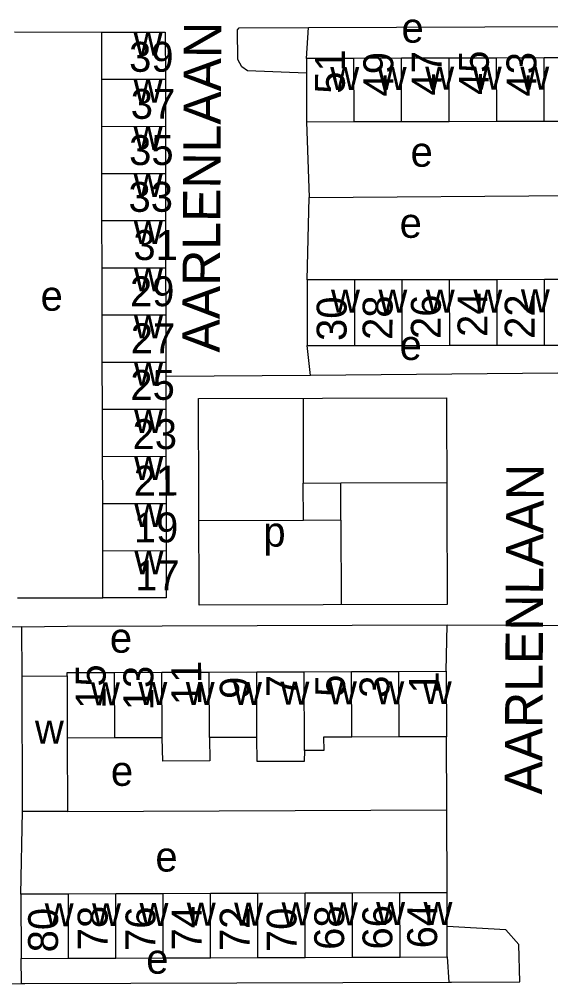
# Model space of a CAD drawing. Extents: x 159675 to 162108, y 386471 to 388472.
# Drawn here: x 161529.2 to 161600.3, y 388087.9 to 388216.9 of the extents above; entities that cross this region are included whole.
import ezdxf

# ---------------------------------------------------------------- set-up
doc = ezdxf.new("R2010")
doc.units = 0
for name, color, linetype in [('BLT_Basislijn', 7, 'Continuous'), ('BLT_Bebouwing', 7, 'Continuous'), ('BLT_Centroide', 7, 'Continuous'), ('BLT_Huisnummer', 7, 'Continuous'), ('BLT_Huisnummer_ tussenligend', 7, 'Continuous'), ('BLT_Onderverdeling_panden', 7, 'Continuous'), ('BLT_Straatnaam', 7, 'Continuous')]:
    doc.layers.add(name, color=color, linetype=linetype)

msp = doc.modelspace()

# ---------------------------------------------------------------- linework, layer by layer
at = {"layer": 'BLT_Basislijn'}
for p, q in [((161567.59, 388211.63), (161567.87, 388215.79)), ((161567.87, 388215.79), (161605.81, 388215.9)), ((161528.53, 388215.18), (161540.24, 388215.17)), ((161567.61, 388203.17), (161567.94, 388193.05)), ((161567.7, 388182.01), (161567.94, 388193.05)), ((161567.94, 388193.05), (161605.87, 388193.33)), ((161568.12, 388169.25), (161567.71, 388173.26)), ((161568.12, 388169.25), (161548.78, 388169.09)), ((161567.14, 388166.19), (161567.17, 388154.85)), ((161567.17, 388154.85), (161572.2, 388154.86)), ((161567.19, 388149.86), (161567.17, 388154.85)), ((161572.2, 388154.86), (161586.34, 388154.91)), ((161572.21, 388149.88), (161572.2, 388154.86)), ((161567.19, 388149.86), (161553.22, 388149.82)), ((161572.21, 388149.88), (161567.19, 388149.86)), ((161572.21, 388149.88), (161572.25, 388138.57)), ((161528.96, 388139.51), (161540.37, 388139.49)), ((161529.58, 388129.04), (161529.54, 388135.64)), ((161586.3, 388129.68), (161586.4, 388135.88)), ((161586.4, 388135.88), (161605.8, 388135.8)), ((161586.37, 388111.14), (161586.34, 388120.92)), ((161529.41, 388099.86), (161529.61, 388110.92)), ((161535.65, 388110.94), (161586.37, 388111.14)), ((161586.4, 388100.05), (161586.37, 388111.14)), ((161586.43, 388091.47), (161586.63, 388088.09)), ((161529.5, 388087.93), (161529.44, 388091.28))]:
    msp.add_line(p, q, dxfattribs=at)
for points in [[(161567.59, 388209.65), (161559.7, 388210), (161558.94, 388210.54), (161558.4, 388211.52), (161558.36, 388215.46), (161558.59, 388215.72), (161567.87, 388215.79)], [(161607.33, 388169.45), (161605.92, 388169.6), (161568.12, 388169.25)], [(161529.54, 388135.64), (161521.68, 388135.58), (161520.91, 388135.58)], [(161529.54, 388135.64), (161535.59, 388135.69), (161586.4, 388135.88)], [(161586.63, 388088.09), (161586.99, 388088.09), (161596.14, 388088.14), (161596.01, 388093.14), (161594.27, 388095.11), (161586.42, 388095.55)], [(161521.72, 388087.89), (161522.06, 388087.89), (161529.5, 388087.93)], [(161529.5, 388087.93), (161529.91, 388087.94), (161586.63, 388088.09)]]:
    msp.add_lwpolyline(points, dxfattribs=at)
msp.add_lwpolyline([(161553.16, 388166.16), (161586.32, 388166.27), (161586.41, 388138.6), (161553.24, 388138.5)], close=True, dxfattribs=at)
at = {"layer": 'BLT_Bebouwing'}
for p, q in [((161540.23, 388208.86), (161540.24, 388215.17)), ((161540.24, 388215.17), (161548.72, 388215.15)), ((161548.72, 388215.15), (161548.73, 388208.88)), ((161573.94, 388211.65), (161567.59, 388211.63)), ((161567.59, 388211.63), (161567.59, 388209.65)), ((161580.3, 388211.67), (161573.94, 388211.65)), ((161586.66, 388211.69), (161580.3, 388211.67)), ((161593.01, 388211.7), (161586.66, 388211.69)), ((161599.37, 388211.72), (161593.01, 388211.7)), ((161605.72, 388211.74), (161599.37, 388211.72)), ((161540.22, 388202.56), (161540.23, 388208.86)), ((161548.73, 388208.88), (161548.74, 388202.57)), ((161567.59, 388209.65), (161567.61, 388203.17)), ((161548.74, 388202.57), (161548.74, 388196.27)), ((161567.61, 388203.17), (161573.97, 388203.19)), ((161573.97, 388203.19), (161580.32, 388203.21)), ((161580.32, 388203.21), (161586.68, 388203.22)), ((161586.68, 388203.22), (161593.04, 388203.24)), ((161593.04, 388203.24), (161599.39, 388203.26)), ((161599.39, 388203.26), (161605.75, 388203.28)), ((161540.24, 388189.95), (161540.23, 388196.25)), ((161548.74, 388196.27), (161548.75, 388189.96)), ((161540.26, 388183.64), (161540.24, 388189.95)), ((161548.75, 388189.96), (161548.76, 388183.65)), ((161540.28, 388177.33), (161540.26, 388183.64)), ((161548.76, 388183.65), (161548.77, 388177.35)), ((161574.05, 388182.02), (161567.7, 388182.01)), ((161567.7, 388182.01), (161567.71, 388173.26)), ((161580.39, 388182.03), (161574.05, 388182.02)), ((161586.74, 388182.04), (161580.39, 388182.03)), ((161593.08, 388182.05), (161586.74, 388182.04)), ((161599.43, 388182.06), (161593.08, 388182.05)), ((161605.77, 388182.07), (161599.43, 388182.06)), ((161540.29, 388171.03), (161540.28, 388177.33)), ((161548.77, 388177.35), (161548.78, 388171.04)), ((161567.71, 388173.26), (161574.06, 388173.27)), ((161574.06, 388173.27), (161580.4, 388173.27)), ((161580.4, 388173.27), (161586.75, 388173.28)), ((161586.75, 388173.28), (161593.09, 388173.29)), ((161593.09, 388173.29), (161599.44, 388173.3)), ((161599.44, 388173.3), (161605.78, 388173.31)), ((161540.31, 388164.72), (161540.29, 388171.03)), ((161548.78, 388171.04), (161548.78, 388169.09)), ((161548.78, 388169.09), (161548.79, 388164.74)), ((161540.32, 388158.42), (161540.31, 388164.72)), ((161548.79, 388164.74), (161548.8, 388158.43)), ((161540.34, 388152.11), (161540.32, 388158.42)), ((161548.8, 388158.43), (161548.81, 388152.12)), ((161540.36, 388145.8), (161540.34, 388152.11)), ((161548.81, 388152.12), (161548.82, 388145.82)), ((161540.37, 388139.49), (161540.36, 388145.8)), ((161529.58, 388129.04), (161535.59, 388129.06)), ((161529.61, 388110.92), (161529.58, 388129.04)), ((161541.92, 388129.52), (161548.26, 388129.55)), ((161548.26, 388129.55), (161554.6, 388129.57)), ((161554.6, 388129.57), (161560.94, 388129.59)), ((161560.94, 388129.59), (161567.28, 388129.61)), ((161567.28, 388129.61), (161573.63, 388129.63)), ((161573.63, 388129.63), (161579.97, 388129.66)), ((161579.97, 388129.66), (161586.3, 388129.68)), ((161586.3, 388129.68), (161586.34, 388120.92)), ((161541.95, 388120.77), (161535.61, 388120.74)), ((161535.61, 388120.74), (161535.65, 388110.94)), ((161548.29, 388120.79), (161541.95, 388120.77)), ((161560.97, 388120.83), (161554.63, 388120.81)), ((161580, 388120.9), (161573.66, 388120.88)), ((161535.75, 388099.88), (161529.41, 388099.86)), ((161529.41, 388099.86), (161529.44, 388091.28)), ((161542.08, 388099.9), (161535.75, 388099.88)), ((161548.41, 388099.92), (161542.08, 388099.9)), ((161554.75, 388099.94), (161548.41, 388099.92)), ((161561.08, 388099.97), (161554.75, 388099.94)), ((161567.41, 388099.99), (161561.08, 388099.97)), ((161573.74, 388100.01), (161567.41, 388099.99)), ((161580.08, 388100.03), (161573.74, 388100.01)), ((161586.4, 388100.05), (161580.08, 388100.03)), ((161586.42, 388095.55), (161586.4, 388100.05)), ((161586.43, 388091.47), (161586.42, 388095.55)), ((161580.11, 388091.45), (161586.43, 388091.47)), ((161529.44, 388091.28), (161535.78, 388091.3)), ((161535.78, 388091.3), (161542.11, 388091.32)), ((161542.11, 388091.32), (161548.44, 388091.34)), ((161548.44, 388091.34), (161554.77, 388091.36)), ((161554.77, 388091.36), (161561.11, 388091.38)), ((161561.11, 388091.38), (161567.44, 388091.41)), ((161567.44, 388091.41), (161573.77, 388091.43)), ((161573.77, 388091.43), (161580.11, 388091.45))]:
    msp.add_line(p, q, dxfattribs=at)
for points in [[(161540.23, 388196.25), (161540.22, 388199.86), (161540.22, 388202.56)], [(161548.82, 388145.82), (161548.82, 388139.52), (161540.37, 388139.49)], [(161535.59, 388129.06), (161535.59, 388129.5), (161541.92, 388129.52)], [(161554.63, 388120.81), (161554.68, 388117.69), (161548.39, 388117.67), (161548.29, 388120.79)], [(161567.32, 388119.07), (161567.3, 388117.61), (161560.99, 388117.59), (161560.97, 388120.83)], [(161573.66, 388120.88), (161569.89, 388120.86), (161569.9, 388119.08), (161567.32, 388119.07)], [(161586.34, 388120.92), (161581.34, 388120.91), (161580, 388120.9)], [(161535.65, 388110.94), (161534.61, 388110.93), (161529.61, 388110.92)]]:
    msp.add_lwpolyline(points, dxfattribs=at)
at = {"layer": 'BLT_Onderverdeling_panden'}
for p, q in [((161573.97, 388203.19), (161573.94, 388211.65)), ((161580.32, 388203.21), (161580.3, 388211.67)), ((161586.68, 388203.22), (161586.66, 388211.69)), ((161593.04, 388203.24), (161593.01, 388211.7)), ((161599.39, 388203.26), (161599.37, 388211.72)), ((161540.23, 388208.86), (161548.73, 388208.88)), ((161540.22, 388202.56), (161548.74, 388202.57)), ((161540.23, 388196.25), (161548.74, 388196.27)), ((161540.24, 388189.95), (161548.75, 388189.96)), ((161540.26, 388183.64), (161548.76, 388183.65)), ((161574.06, 388173.27), (161574.05, 388182.02)), ((161580.4, 388173.27), (161580.39, 388182.03)), ((161586.75, 388173.28), (161586.74, 388182.04)), ((161593.09, 388173.29), (161593.08, 388182.05)), ((161599.44, 388173.3), (161599.43, 388182.06)), ((161540.28, 388177.33), (161548.77, 388177.35)), ((161540.29, 388171.03), (161548.78, 388171.04)), ((161540.31, 388164.72), (161548.79, 388164.74)), ((161540.32, 388158.42), (161548.8, 388158.43)), ((161540.34, 388152.11), (161548.81, 388152.12)), ((161540.36, 388145.8), (161548.82, 388145.82)), ((161535.59, 388129.06), (161535.61, 388120.74)), ((161541.95, 388120.77), (161541.92, 388129.52)), ((161548.29, 388120.79), (161548.26, 388129.55)), ((161554.63, 388120.81), (161554.6, 388129.57)), ((161560.97, 388120.83), (161560.94, 388129.59)), ((161567.32, 388119.07), (161567.28, 388129.61)), ((161573.66, 388120.88), (161573.63, 388129.63)), ((161580, 388120.9), (161579.97, 388129.66)), ((161535.78, 388091.3), (161535.75, 388099.88)), ((161542.11, 388091.32), (161542.08, 388099.9)), ((161548.44, 388091.34), (161548.41, 388099.92)), ((161554.77, 388091.36), (161554.75, 388099.94)), ((161561.11, 388091.38), (161561.08, 388099.97)), ((161567.44, 388091.41), (161567.41, 388099.99)), ((161573.77, 388091.43), (161573.74, 388100.01)), ((161580.11, 388091.45), (161580.08, 388100.03))]:
    msp.add_line(p, q, dxfattribs=at)

# ---------------------------------------------------------------- texts
at = {"layer": 'BLT_Centroide'}
for s, p in [('e', (161580.31, 388213.75)), ('w', (161544.48, 388212.03)), ('w', (161570.78, 388207.41)), ('w', (161577.12, 388207.42)), ('w', (161583.48, 388207.45)), ('w', (161589.84, 388207.45)), ('w', (161596.2, 388207.48)), ('w', (161544.48, 388205.72)), ('w', (161544.48, 388199.41)), ('e', (161581.52, 388197.16)), ('w', (161544.49, 388193.09)), ('e', (161580.06, 388187.65)), ('w', (161544.51, 388186.81)), ('w', (161544.52, 388180.5)), ('e', (161532.04, 388177.9)), ('w', (161570.88, 388177.64)), ('w', (161577.22, 388177.66)), ('w', (161583.56, 388177.66)), ('w', (161589.92, 388177.66)), ('w', (161596.27, 388177.69)), ('w', (161544.53, 388174.19)), ('e', (161580.06, 388171.31)), ('w', (161544.54, 388167.88)), ('w', (161544.55, 388161.56)), ('w', (161544.56, 388155.28)), ('w', (161544.58, 388148.97)), ('p', (161561.83, 388146.35)), ('w', (161544.59, 388142.66)), ('e', (161541.3, 388132.16)), ('w', (161538.77, 388125.12)), ('w', (161545.11, 388125.16)), ('w', (161551.45, 388125.19)), ('w', (161557.78, 388125.19)), ('w', (161564.12, 388125.22)), ('w', (161570.47, 388125.25)), ('w', (161576.81, 388125.27)), ('w', (161583.16, 388125.28)), ('w', (161531.28, 388120)), ('e', (161541.44, 388114.35)), ('e', (161547.39, 388102.89)), ('w', (161532.59, 388095.58)), ('w', (161538.92, 388095.59)), ('w', (161545.27, 388095.62)), ('w', (161551.59, 388095.64)), ('w', (161557.92, 388095.67)), ('w', (161564.27, 388095.69)), ('w', (161570.59, 388095.7)), ('w', (161576.92, 388095.73)), ('w', (161583.25, 388095.75)), ('e', (161546.17, 388089.23))]:
    msp.add_text(s, height=4, dxfattribs=at).set_placement(p)
at = {"layer": 'BLT_Huisnummer'}
for s, rotation, p in [('39', 0.183, (161543.88, 388209.85)), ('51', 89.8307, (161572.72, 388206.92)), ('45', 89.8307, (161591.97, 388206.74)), ('33', 0.183, (161543.8, 388191.12)), ('29', 0.183, (161544, 388178.49)), ('30', 89.9149, (161572.96, 388173.85)), ('24', 89.9149, (161591.8, 388174.39)), ('25', 0.183, (161544.05, 388165.97)), ('21', 0.183, (161544.5, 388153.17)), ('17', 0.183, (161544.69, 388140.51)), ('15', 89.7972, (161540.72, 388124.65)), ('5', 89.7972, (161572.76, 388126.25)), ('1', 89.7972, (161585.29, 388126.68)), ('9', 89.7972, (161560, 388125.97)), ('76', 89.813, (161547.38, 388092.26)), ('72', 89.813, (161559.98, 388092.25)), ('68', 89.813, (161572.63, 388092.41)), ('64', 89.813, (161585.07, 388092.62)), ('80', 89.813, (161534.36, 388092.08))]:
    msp.add_text(s, height=4, rotation=rotation, dxfattribs=at).set_placement(p)
at = {"layer": 'BLT_Huisnummer_ tussenligend'}
for s, rotation, p in [('49', 90.1693, (161579.22, 388206.56)), ('47', 90.1693, (161585.69, 388206.68)), ('43', 90.1693, (161598.36, 388206.56)), ('37', 0.0949, (161544.1, 388203.56)), ('35', 0.0949, (161543.88, 388197.38)), ('31', 0.0949, (161544.45, 388184.68)), ('28', 89.9149, (161579.1, 388173.99)), ('26', 89.9149, (161585.56, 388174.11)), ('22', 89.9149, (161598.11, 388174.13)), ('27', 0.0949, (161544.1, 388172.21)), ('23', 0.0949, (161544.34, 388159.39)), ('19', 0.0949, (161544.51, 388146.91)), ('13', 90.2029, (161547.13, 388124.47)), ('11', 90.2029, (161553.53, 388125.15)), ('7', 90.2029, (161566.23, 388126.24)), ('3', 90.203, (161578.7, 388126.14)), ('78', 90.1938, (161541.01, 388092.37)), ('74', 90.1938, (161553.58, 388092.36)), ('66', 90.1938, (161579.09, 388092.47)), ('70', 90.1938, (161566.28, 388092.13))]:
    msp.add_text(s, height=4, rotation=rotation, dxfattribs=at).set_placement(p)
at = {"layer": 'BLT_Straatnaam'}
for p in [(161555.98, 388172.3), (161599.11, 388113.17)]:
    msp.add_text('AARLENLAAN', height=5, rotation=89.6999, dxfattribs=at).set_placement(p)

doc.saveas('drawing.dxf')
